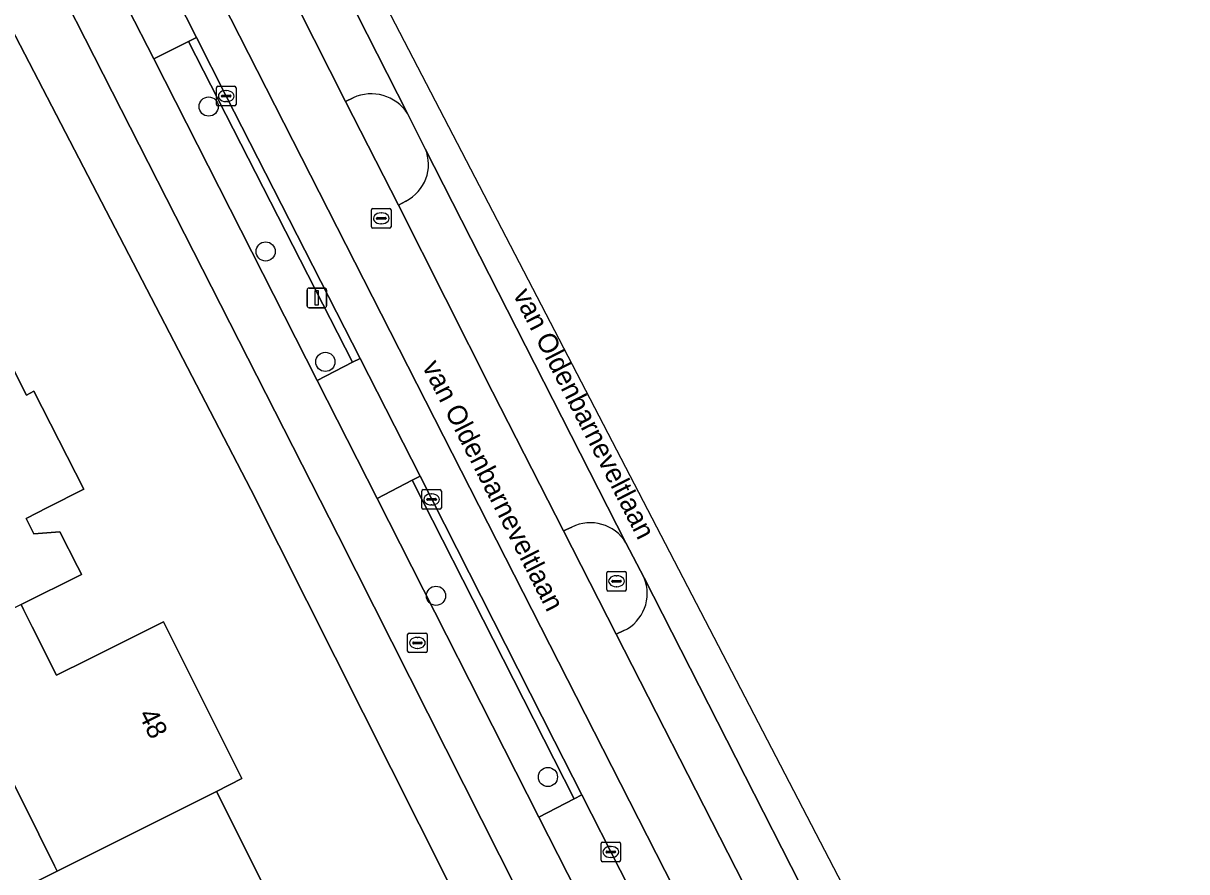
# Model space of a CAD drawing. Extents: x 162417 to 163722, y 384268 to 385417.
# Drawn here: x 163607.6 to 163666.9, y 384859.9 to 384903.2 of the extents above; entities that cross this region are included whole.
import ezdxf

# ---------------------------------------------------------------- set-up
doc = ezdxf.new("R2010")
doc.units = 0
for name, color, linetype in [('IMGEO_Berm_groen', 7, 'Continuous'), ('IMGEO_Boom', 7, 'Continuous'), ('IMGEO_Erf', 7, 'Continuous'), ('IMGEO_Fietspad_open', 7, 'Continuous'), ('IMGEO_Kolk', 7, 'Continuous'), ('IMGEO_Lichtmast', 7, 'Continuous'), ('IMGEO_Openbare_ruimte_label', 7, 'Continuous'), ('IMGEO_Pand', 7, 'Continuous'), ('IMGEO_Pand_nummerreeks', 7, 'Continuous'), ('IMGEO_Parkeervlak_open', 7, 'Continuous'), ('IMGEO_Rijbaan_lokaal_gesloten', 7, 'Continuous'), ('IMGEO_Rioolput', 7, 'Continuous'), ('IMGEO_Verkeerseiland_groen', 7, 'Continuous'), ('IMGEO_Voetpad_open', 7, 'Continuous')]:
    doc.layers.add(name, color=color, linetype=linetype)

msp = doc.modelspace()

# ---------------------------------------------------------------- linework, layer by layer
at = {"layer": 'IMGEO_Berm_groen'}
for points in [[(163616.021, 384902.255), (163614.241, 384901.371), (163622.577, 384884.967), (163624.387, 384885.901)], [(163627.432, 384879.887), (163625.634, 384878.951), (163633.891, 384862.701), (163635.688, 384863.627)]]:
    msp.add_lwpolyline(points, close=True, dxfattribs=at)
at = {"layer": 'IMGEO_Boom'}
for centre in [(163617.045, 384898.941), (163619.952, 384891.548), (163623, 384885.916), (163628.641, 384873.986), (163634.352, 384864.743)]:
    msp.add_circle(centre, 0.489, dxfattribs=at)
at = {"layer": 'IMGEO_Erf'}
for points in [[(163552.107, 384845.87), (163579.211, 384794.807), (163618.849, 384814.904), (163626.367, 384818.629), (163626.635, 384818.288), (163641.667, 384825.959), (163641.486, 384826.348), (163644.977, 384828.162), (163619.201, 384879.411), (163599.332, 384917.655), (163572.96, 384969.64), (163571.782, 384971.962), (163557.559, 385000)], [(163606.455, 384886.772), (163607.752, 384884.227), (163608.126, 384884.417), (163610.67, 384879.423), (163608.828, 384878.485), (163607.732, 384877.927), (163608.132, 384877.143), (163609.455, 384877.256), (163610.361, 384875.481), (163610.473, 384875.261), (163610.567, 384875.078), (163607.479, 384873.535), (163607.602, 384873.289), (163608.047, 384872.398), (163609.28, 384869.932), (163610.899, 384870.741), (163614.745, 384872.663), (163618.745, 384864.66), (163617.444, 384864.01), (163621.195, 384856.505)], [(163608.019, 384859.3), (163609.312, 384859.946), (163609.177, 384860.216), (163608.375, 384861.82), (163606.324, 384865.924)]]:
    msp.add_lwpolyline(points, dxfattribs=at)
at = {"layer": 'IMGEO_Fietspad_open'}
for points in [[(163597.182, 384934.928), (163591.881, 384945.373), (163587.17, 384954.629), (163580.11, 384968.571), (163582.666, 384969.844), (163581.6, 384972.726), (163578.743, 384971.268), (163576.974, 384974.74), (163574.621, 384973.481), (163577.374, 384968.061), (163596.886, 384929.577), (163623.647, 384877.065), (163632.793, 384858.931), (163649.142, 384826.839), (163653.17, 384818.952), (163659.857, 384805.917), (163666.533, 384792.914), (163666.937, 384792.116)], [(163639.718, 384851.234), (163633.891, 384862.701), (163625.634, 384878.951), (163622.577, 384884.967), (163614.241, 384901.371), (163611.636, 384906.498), (163602.548, 384924.382), (163599.53, 384930.319), (163602.255, 384931.739), (163600.272, 384934.695)]]:
    msp.add_lwpolyline(points, dxfattribs=at)
at = {"layer": 'IMGEO_Kolk'}
for p, q in [((163617.44, 384899.049), (163617.44, 384899.901)), ((163617.515, 384899.975), (163618.367, 384899.975)), ((163617.928, 384899.755), (163617.953, 384899.755)), ((163618.441, 384899.901), (163618.441, 384899.049)), ((163617.699, 384899.469), (163617.699, 384899.481)), ((163618.137, 384899.432), (163617.739, 384899.432)), ((163617.742, 384899.518), (163618.14, 384899.518)), ((163617.951, 384899.195), (163617.926, 384899.195)), ((163618.183, 384899.481), (163618.183, 384899.469)), ((163618.367, 384898.975), (163617.515, 384898.975)), ((163627.918, 384878.475), (163627.918, 384879.327)), ((163627.993, 384879.401), (163628.845, 384879.401)), ((163628.177, 384878.895), (163628.177, 384878.907)), ((163628.22, 384878.944), (163628.618, 384878.944)), ((163628.406, 384879.181), (163628.431, 384879.181)), ((163628.661, 384878.907), (163628.661, 384878.895)), ((163628.919, 384879.327), (163628.919, 384878.475)), ((163628.845, 384878.401), (163627.993, 384878.401)), ((163628.615, 384878.858), (163628.217, 384878.858)), ((163628.429, 384878.621), (163628.404, 384878.621)), ((163637.06, 384860.493), (163637.06, 384861.345)), ((163637.135, 384861.419), (163637.987, 384861.419)), ((163637.548, 384861.199), (163637.573, 384861.199)), ((163638.061, 384861.345), (163638.061, 384860.493)), ((163637.319, 384860.913), (163637.319, 384860.925)), ((163637.757, 384860.876), (163637.359, 384860.876)), ((163637.362, 384860.962), (163637.76, 384860.962)), ((163637.571, 384860.639), (163637.546, 384860.639)), ((163637.803, 384860.925), (163637.803, 384860.913)), ((163637.987, 384860.419), (163637.135, 384860.419))]:
    msp.add_line(p, q, dxfattribs=at)
for points in [[(163617.44, 384899.049), (163617.44, 384899.901)], [(163617.515, 384899.975), (163618.367, 384899.975)], [(163618.441, 384899.901), (163618.441, 384899.049)], [(163618.367, 384898.975), (163617.515, 384898.975)], [(163627.918, 384878.475), (163627.918, 384879.327)], [(163627.993, 384879.401), (163628.845, 384879.401)], [(163628.919, 384879.327), (163628.919, 384878.475)], [(163628.845, 384878.401), (163627.993, 384878.401)], [(163637.06, 384860.493), (163637.06, 384861.345)], [(163637.135, 384861.419), (163637.987, 384861.419)], [(163638.061, 384861.345), (163638.061, 384860.493)], [(163637.987, 384860.419), (163637.135, 384860.419)]]:
    msp.add_lwpolyline(points, dxfattribs=at)
for centre, radius, start, end in [((163617.517, 384899.899), 0.0765, 91.55205, 178.44795), ((163617.517, 384899.899), 0.0765, 91.55205, 178.44795), ((163618.365, 384899.899), 0.0765, 1.55205, 88.44795), ((163618.365, 384899.899), 0.0765, 1.55205, 88.44795), ((163617.739, 384899.478), 0.0403, 85.87752, 175.75265), ((163617.736, 384899.468), 0.0366, 178.93798, 274.71019), ((163618.14, 384899.475), 0.043, 264.86636, 352.45326), ((163618.144, 384899.48), 0.0386, 1.73085, 96.63898), ((163617.517, 384899.051), 0.0765, 181.55205, 268.44795), ((163617.517, 384899.051), 0.0765, 181.55205, 268.44795), ((163618.365, 384899.051), 0.0765, 271.55205, 358.44795), ((163618.365, 384899.051), 0.0765, 271.55205, 358.44795), ((163627.995, 384879.325), 0.0765, 91.55205, 178.44795), ((163627.995, 384879.325), 0.0765, 91.55205, 178.44795), ((163628.217, 384878.904), 0.0403, 85.87752, 175.75265), ((163628.622, 384878.906), 0.0386, 1.73085, 96.63898), ((163628.843, 384879.325), 0.0765, 1.55205, 88.44795), ((163628.843, 384879.325), 0.0765, 1.55205, 88.44795), ((163627.995, 384878.477), 0.0765, 181.55205, 268.44795), ((163627.995, 384878.477), 0.0765, 181.55205, 268.44795), ((163628.214, 384878.894), 0.0366, 178.93798, 274.71019), ((163628.618, 384878.901), 0.043, 264.86636, 352.45326), ((163628.843, 384878.477), 0.0765, 271.55205, 358.44795), ((163628.843, 384878.477), 0.0765, 271.55205, 358.44795), ((163637.137, 384861.343), 0.0765, 91.55205, 178.44795), ((163637.137, 384861.343), 0.0765, 91.55205, 178.44795), ((163637.985, 384861.343), 0.0765, 1.55205, 88.44795), ((163637.985, 384861.343), 0.0765, 1.55205, 88.44795), ((163637.359, 384860.922), 0.0403, 85.87752, 175.75265), ((163637.356, 384860.912), 0.0366, 178.93798, 274.71019), ((163637.76, 384860.919), 0.043, 264.86636, 352.45326), ((163637.764, 384860.924), 0.0386, 1.73085, 96.63898), ((163637.137, 384860.495), 0.0765, 181.55205, 268.44795), ((163637.137, 384860.495), 0.0765, 181.55205, 268.44795), ((163637.985, 384860.495), 0.0765, 271.55205, 358.44795), ((163637.985, 384860.495), 0.0765, 271.55205, 358.44795)]:
    msp.add_arc(centre, radius, start, end, dxfattribs=at)
for centre, major_axis, ratio, start_param, end_param in [((163617.927, 384899.475), (-0.387, 0.002), 0.722429, 4.712389, 7.853982), ((163617.952, 384899.475), (-0.39, 0.002), 0.717154, 1.570796, 4.712389), ((163628.405, 384878.901), (-0.387, 0.002), 0.722429, 4.712389, 7.853982), ((163628.43, 384878.901), (-0.39, 0.002), 0.717154, 1.570796, 4.712389), ((163637.547, 384860.919), (-0.387, 0.002), 0.722429, 4.712389, 7.853982), ((163637.572, 384860.919), (-0.39, 0.002), 0.717154, 1.570796, 4.712389)]:
    msp.add_ellipse(centre, major_axis=major_axis, ratio=ratio, start_param=start_param, end_param=end_param, dxfattribs=at)
at = {"layer": 'IMGEO_Lichtmast'}
for p, q in [((163622.167, 384889.682), (163622.957, 384889.682)), ((163622.957, 384889.682), (163622.167, 384889.682)), ((163622.067, 384888.782), (163622.067, 384889.582)), ((163622.067, 384889.582), (163622.067, 384888.782)), ((163623.057, 384889.582), (163623.057, 384888.782)), ((163623.057, 384888.782), (163623.057, 384889.582)), ((163622.957, 384888.682), (163622.167, 384888.682)), ((163622.167, 384888.682), (163622.957, 384888.682))]:
    msp.add_line(p, q, dxfattribs=at)
msp.add_lwpolyline([(163622.487, 384889.557), (163622.637, 384889.557), (163622.637, 384888.807), (163622.487, 384888.807), (163622.487, 384889.557)], dxfattribs=at)
for centre, start, end in [((163622.167, 384889.582), 90, 180), ((163622.167, 384889.582), 90, 180), ((163622.957, 384889.582), 0, 90), ((163622.957, 384889.582), 360, 90), ((163622.167, 384888.782), 180, 270), ((163622.167, 384888.782), 180, 270), ((163622.957, 384888.782), 270, 0), ((163622.957, 384888.782), 270, 0)]:
    msp.add_arc(centre, 0.1, start, end, dxfattribs=at)
at = {"layer": 'IMGEO_Pand'}
msp.add_lwpolyline([(163607.479, 384873.535), (163610.567, 384875.078), (163610.473, 384875.261), (163610.361, 384875.481), (163609.455, 384877.256), (163608.132, 384877.143), (163607.732, 384877.927), (163608.828, 384878.485), (163610.67, 384879.423), (163608.126, 384884.417), (163607.752, 384884.227), (163606.455, 384886.772)], dxfattribs=at)
for points in [[(163607.479, 384873.535), (163604.553, 384872.073), (163599.877, 384869.735), (163599.444, 384869.519), (163602.257, 384863.891), (163606.324, 384865.924), (163608.375, 384861.82), (163609.177, 384860.216), (163609.312, 384859.946), (163617.444, 384864.01), (163618.745, 384864.66), (163614.745, 384872.663), (163610.899, 384870.741), (163609.28, 384869.932), (163608.047, 384872.398), (163607.602, 384873.289)], [(163621.195, 384856.505), (163617.444, 384864.01), (163609.312, 384859.946), (163608.019, 384859.3), (163610.77, 384853.794), (163608.165, 384852.491), (163611.09, 384846.64), (163613.323, 384847.756), (163617.795, 384849.991), (163615.87, 384853.843), (163617.34, 384854.578)]]:
    msp.add_lwpolyline(points, close=True, dxfattribs=at)
at = {"layer": 'IMGEO_Parkeervlak_open'}
for points in [[(163607.819, 384919.356), (163613.799, 384907.626), (163616.433, 384902.46), (163617.944, 384899.472), (163624.767, 384886.097), (163627.83, 384880.094), (163634.679, 384866.567), (163636.076, 384863.827), (163641.952, 384852.31), (163650.663, 384835.261)], [(163653.554, 384833.868), (163649.36, 384842.217), (163615.458, 384908.764)]]:
    msp.add_lwpolyline(points, dxfattribs=at)
at = {"layer": 'IMGEO_Rijbaan_lokaal_gesloten'}
for points in [[(163661.347, 384836.226), (163619.127, 384917.491), (163613.318, 384931.873), (163611.199, 384930.781)], [(163654.435, 384839.414), (163649.222, 384849.714), (163637.836, 384872.021), (163635.147, 384877.295), (163631.529, 384884.39), (163626.726, 384893.906), (163624.028, 384899.194), (163616.06, 384914.963), (163612.446, 384921.707)], [(163616.792, 384919.054), (163617.371, 384917.896), (163627.181, 384898.586), (163628.097, 384896.793), (163638.331, 384876.691), (163639.256, 384874.898), (163652.368, 384849.162), (163653.268, 384847.508), (163656.873, 384840.904), (163659.964, 384835.538), (163661.347, 384836.226)], [(163615.458, 384908.764), (163649.36, 384842.217), (163653.554, 384833.868), (163654.225, 384832.489), (163657.078, 384834.025)]]:
    msp.add_lwpolyline(points, dxfattribs=at)
at = {"layer": 'IMGEO_Rioolput'}
for p, q in [((163625.425, 384893.739), (163626.277, 384893.739)), ((163625.35, 384892.813), (163625.35, 384893.665)), ((163625.609, 384893.233), (163625.609, 384893.245)), ((163626.047, 384893.196), (163625.649, 384893.196)), ((163625.652, 384893.282), (163626.05, 384893.282)), ((163625.838, 384893.519), (163625.863, 384893.519)), ((163626.093, 384893.245), (163626.093, 384893.233)), ((163626.351, 384893.665), (163626.351, 384892.813)), ((163626.277, 384892.739), (163625.425, 384892.739)), ((163625.861, 384892.959), (163625.836, 384892.959)), ((163637.35, 384874.303), (163637.35, 384875.155)), ((163637.425, 384875.229), (163638.277, 384875.229)), ((163637.652, 384874.772), (163638.05, 384874.772)), ((163637.838, 384875.009), (163637.863, 384875.009)), ((163638.351, 384875.155), (163638.351, 384874.303)), ((163638.277, 384874.229), (163637.425, 384874.229)), ((163637.609, 384874.723), (163637.609, 384874.735)), ((163638.047, 384874.686), (163637.649, 384874.686)), ((163637.861, 384874.449), (163637.836, 384874.449)), ((163638.093, 384874.735), (163638.093, 384874.723)), ((163627.195, 384871.159), (163627.195, 384872.011)), ((163627.27, 384872.085), (163628.122, 384872.085)), ((163627.683, 384871.865), (163627.708, 384871.865)), ((163628.196, 384872.011), (163628.196, 384871.159)), ((163627.454, 384871.579), (163627.454, 384871.591)), ((163627.892, 384871.542), (163627.494, 384871.542)), ((163627.497, 384871.628), (163627.895, 384871.628)), ((163627.706, 384871.305), (163627.681, 384871.305)), ((163627.938, 384871.591), (163627.938, 384871.579)), ((163628.122, 384871.085), (163627.27, 384871.085))]:
    msp.add_line(p, q, dxfattribs=at)
for points in [[(163625.425, 384893.739), (163626.277, 384893.739)], [(163625.35, 384892.813), (163625.35, 384893.665)], [(163626.351, 384893.665), (163626.351, 384892.813)], [(163626.277, 384892.739), (163625.425, 384892.739)], [(163637.35, 384874.303), (163637.35, 384875.155)], [(163637.425, 384875.229), (163638.277, 384875.229)], [(163638.351, 384875.155), (163638.351, 384874.303)], [(163638.277, 384874.229), (163637.425, 384874.229)], [(163627.195, 384871.159), (163627.195, 384872.011)], [(163627.27, 384872.085), (163628.122, 384872.085)], [(163628.196, 384872.011), (163628.196, 384871.159)], [(163628.122, 384871.085), (163627.27, 384871.085)]]:
    msp.add_lwpolyline(points, dxfattribs=at)
for centre, radius, start, end in [((163625.427, 384893.663), 0.0765, 91.55205, 178.44795), ((163625.427, 384893.663), 0.0765, 91.55205, 178.44795), ((163626.275, 384893.663), 0.0765, 1.55205, 88.44795), ((163626.275, 384893.663), 0.0765, 1.55205, 88.44795), ((163625.649, 384893.242), 0.0403, 85.87752, 175.75265), ((163625.646, 384893.232), 0.0366, 178.93798, 274.71019), ((163626.05, 384893.239), 0.043, 264.86636, 352.45326), ((163626.054, 384893.244), 0.0386, 1.73085, 96.63898), ((163625.427, 384892.815), 0.0765, 181.55205, 268.44795), ((163625.427, 384892.815), 0.0765, 181.55205, 268.44795), ((163626.275, 384892.815), 0.0765, 271.55205, 358.44795), ((163626.275, 384892.815), 0.0765, 271.55205, 358.44795), ((163637.427, 384875.153), 0.0765, 91.55205, 178.44795), ((163637.427, 384875.153), 0.0765, 91.55205, 178.44795), ((163637.649, 384874.732), 0.0403, 85.87752, 175.75265), ((163638.054, 384874.734), 0.0386, 1.73085, 96.63898), ((163638.275, 384875.153), 0.0765, 1.55205, 88.44795), ((163638.275, 384875.153), 0.0765, 1.55205, 88.44795), ((163637.427, 384874.305), 0.0765, 181.55205, 268.44795), ((163637.427, 384874.305), 0.0765, 181.55205, 268.44795), ((163637.646, 384874.722), 0.0366, 178.93798, 274.71019), ((163638.05, 384874.729), 0.043, 264.86636, 352.45326), ((163638.275, 384874.305), 0.0765, 271.55205, 358.44795), ((163638.275, 384874.305), 0.0765, 271.55205, 358.44795), ((163627.272, 384872.009), 0.0765, 91.55205, 178.44795), ((163627.272, 384872.009), 0.0765, 91.55205, 178.44795), ((163628.12, 384872.009), 0.0765, 1.55205, 88.44795), ((163628.12, 384872.009), 0.0765, 1.55205, 88.44795), ((163627.494, 384871.588), 0.0403, 85.87752, 175.75265), ((163627.491, 384871.578), 0.0366, 178.93798, 274.71019), ((163627.895, 384871.585), 0.043, 264.86636, 352.45326), ((163627.899, 384871.59), 0.0386, 1.73085, 96.63898), ((163627.272, 384871.161), 0.0765, 181.55205, 268.44795), ((163627.272, 384871.161), 0.0765, 181.55205, 268.44795), ((163628.12, 384871.161), 0.0765, 271.55205, 358.44795), ((163628.12, 384871.161), 0.0765, 271.55205, 358.44795)]:
    msp.add_arc(centre, radius, start, end, dxfattribs=at)
for centre, major_axis, ratio, start_param, end_param in [((163625.837, 384893.239), (-0.387, 0.002), 0.722429, 4.712389, 7.853982), ((163625.862, 384893.239), (-0.39, 0.002), 0.717154, 1.570796, 4.712389), ((163637.837, 384874.729), (-0.387, 0.002), 0.722429, 4.712389, 7.853982), ((163637.862, 384874.729), (-0.39, 0.002), 0.717154, 1.570796, 4.712389), ((163627.682, 384871.585), (-0.387, 0.002), 0.722429, 4.712389, 7.853982), ((163627.707, 384871.585), (-0.39, 0.002), 0.717154, 1.570796, 4.712389)]:
    msp.add_ellipse(centre, major_axis=major_axis, ratio=ratio, start_param=start_param, end_param=end_param, dxfattribs=at)
at = {"layer": 'IMGEO_Verkeerseiland_groen'}
for points in [[(163624.418, 384899.391), (163624.028, 384899.194), (163626.726, 384893.906), (163627.103, 384894.122)], [(163628.097, 384896.793), (163627.181, 384898.586)], [(163635.564, 384877.485), (163635.147, 384877.295), (163637.836, 384872.021), (163638.225, 384872.209)], [(163639.256, 384874.898), (163638.331, 384876.691)]]:
    msp.add_lwpolyline(points, dxfattribs=at)
for centre, radius, start, end in [((163625.334, 384897.391), 2.2, 32.91153, 114.60151), ((163626.178, 384895.987), 2.081, 296.37867, 22.79631), ((163636.518, 384875.59), 2.122, 31.26937, 116.7086), ((163637.334, 384874.093), 2.083, 295.30344, 22.74152)]:
    msp.add_arc(centre, radius, start, end, dxfattribs=at)
at = {"layer": 'IMGEO_Voetpad_open'}
for points in [[(163531.103, 385052.107), (163533.125, 385048.062), (163534.443, 385045.503), (163557.559, 385000), (163571.782, 384971.962), (163572.96, 384969.64), (163599.332, 384917.655), (163619.201, 384879.411), (163644.977, 384828.162), (163646.209, 384825.591), (163647.107, 384826.065), (163654.204, 384812.214), (163656.997, 384806.824), (163660.571, 384799.786), (163661.604, 384797.609), (163662.207, 384797.874), (163664.204, 384793.9), (163665.062, 384792.193), (163665.979, 384790.369)], [(163653.17, 384818.952), (163649.142, 384826.839), (163632.793, 384858.931), (163623.647, 384877.065), (163596.886, 384929.577), (163577.374, 384968.061), (163574.621, 384973.481), (163547.457, 385026.967), (163540.137, 385041.23), (163534.186, 385050.269), (163533.893, 385050.706)], [(163627.181, 384898.586), (163617.371, 384917.896)], [(163616.456, 384915.183), (163616.06, 384914.963), (163624.028, 384899.194), (163624.418, 384899.391)], [(163638.331, 384876.691), (163628.097, 384896.793)], [(163627.103, 384894.122), (163626.726, 384893.906), (163631.529, 384884.39), (163635.147, 384877.295), (163635.564, 384877.485)], [(163652.368, 384849.162), (163639.256, 384874.898)], [(163638.225, 384872.209), (163637.836, 384872.021), (163649.222, 384849.714)]]:
    msp.add_lwpolyline(points, dxfattribs=at)
for points in [[(163616.021, 384902.255), (163616.433, 384902.46), (163613.799, 384907.626), (163613.376, 384907.405), (163611.636, 384906.498), (163614.241, 384901.371)], [(163616.021, 384902.255), (163624.387, 384885.901), (163624.767, 384886.097), (163617.944, 384899.472), (163616.433, 384902.46)], [(163624.767, 384886.097), (163624.387, 384885.901), (163622.577, 384884.967), (163625.634, 384878.951), (163627.432, 384879.887), (163627.83, 384880.094)], [(163635.688, 384863.627), (163636.076, 384863.827), (163634.679, 384866.567), (163627.83, 384880.094), (163627.432, 384879.887)], [(163641.952, 384852.31), (163636.076, 384863.827), (163635.688, 384863.627), (163633.891, 384862.701), (163639.718, 384851.234), (163641.549, 384852.109)]]:
    msp.add_lwpolyline(points, close=True, dxfattribs=at)
for centre, radius, start, end in [((163625.334, 384897.391), 2.2, 32.91153, 114.60151), ((163626.178, 384895.987), 2.081, 296.37867, 22.79631), ((163636.518, 384875.59), 2.122, 31.26937, 116.7086), ((163637.334, 384874.093), 2.083, 295.30344, 22.74152)]:
    msp.add_arc(centre, radius, start, end, dxfattribs=at)

# ---------------------------------------------------------------- texts
at = {"layer": 'IMGEO_Openbare_ruimte_label'}
for rotation, p in [(297.05168, (163632.551, 384889.354)), (297.00065, (163627.921, 384885.688))]:
    msp.add_text('van Oldenbarneveltlaan', height=1, rotation=rotation, dxfattribs=at).set_placement(p)
at = {"layer": 'IMGEO_Pand_nummerreeks'}
msp.add_text('48', height=1, rotation=296.55638, dxfattribs=at).set_placement((163613.443, 384867.931))

doc.saveas('drawing.dxf')
